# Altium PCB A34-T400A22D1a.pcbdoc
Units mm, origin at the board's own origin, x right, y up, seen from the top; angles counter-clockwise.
Board outline 74.15 x 49.73 mm, 2 copper layers (Top Layer, Bottom Layer); 2 components, 7 nets, 10 pads, 0 vias.
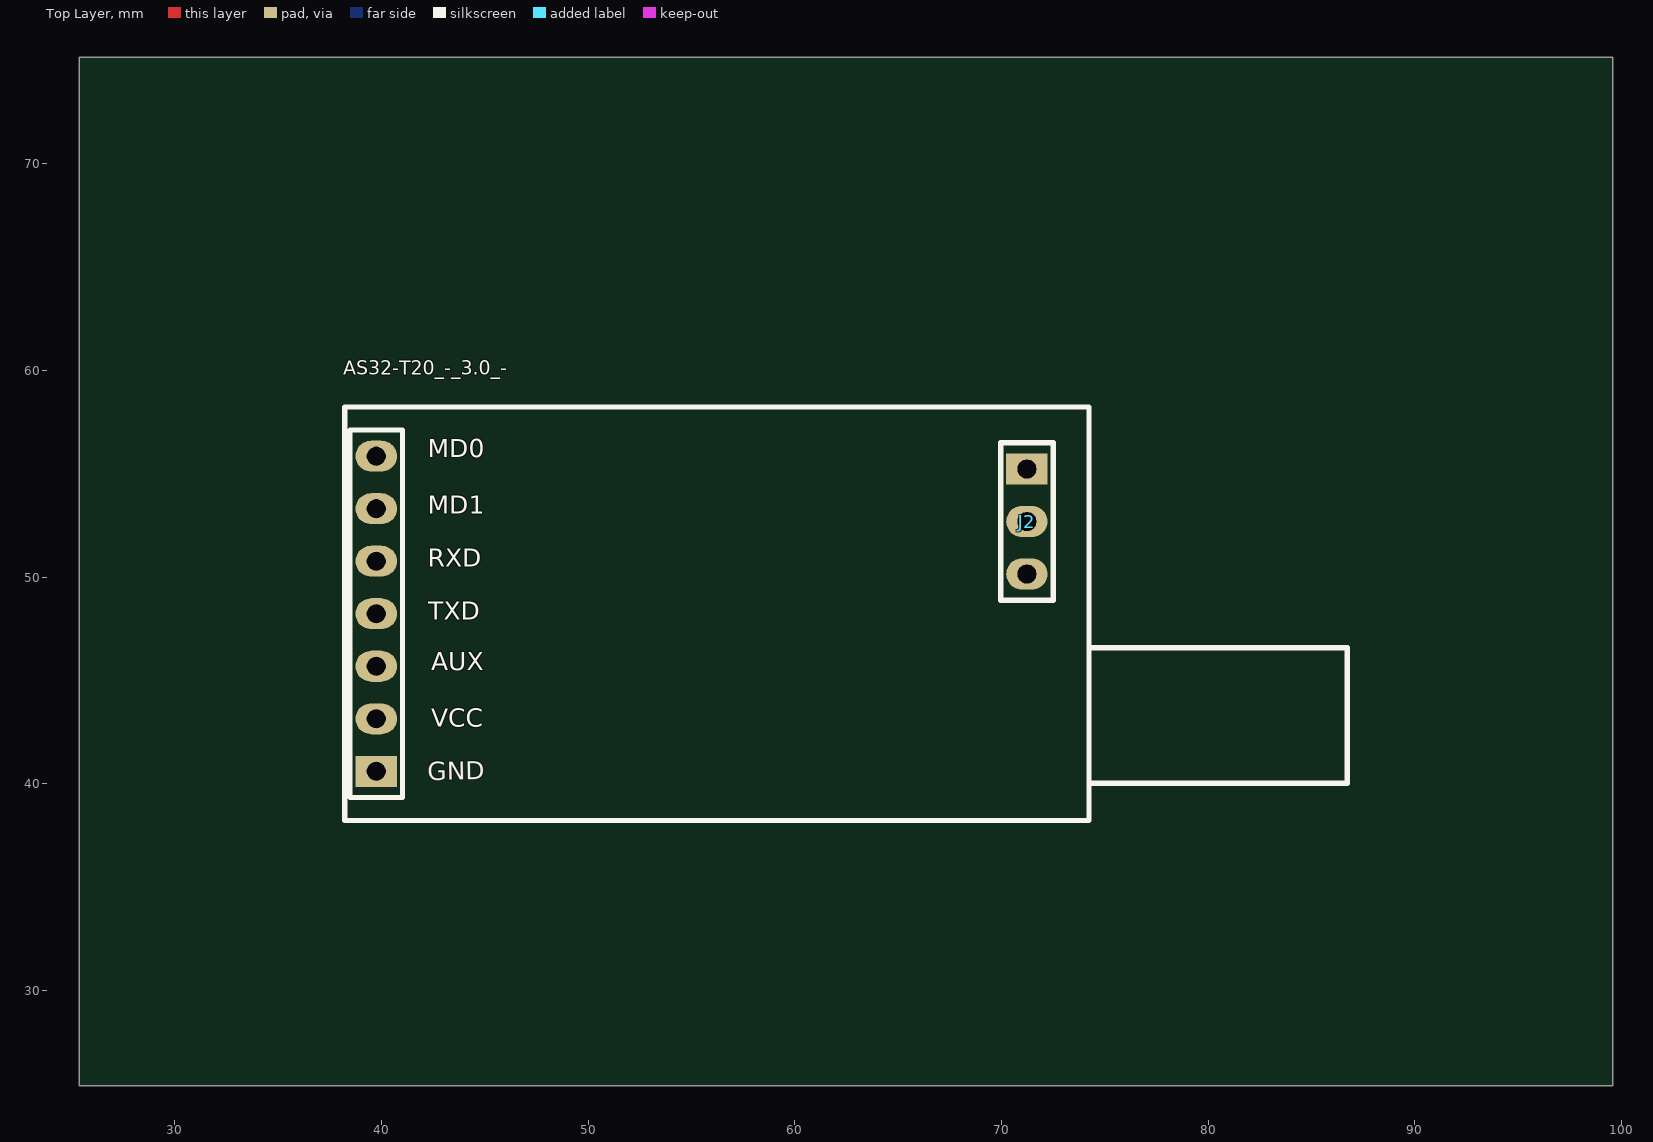
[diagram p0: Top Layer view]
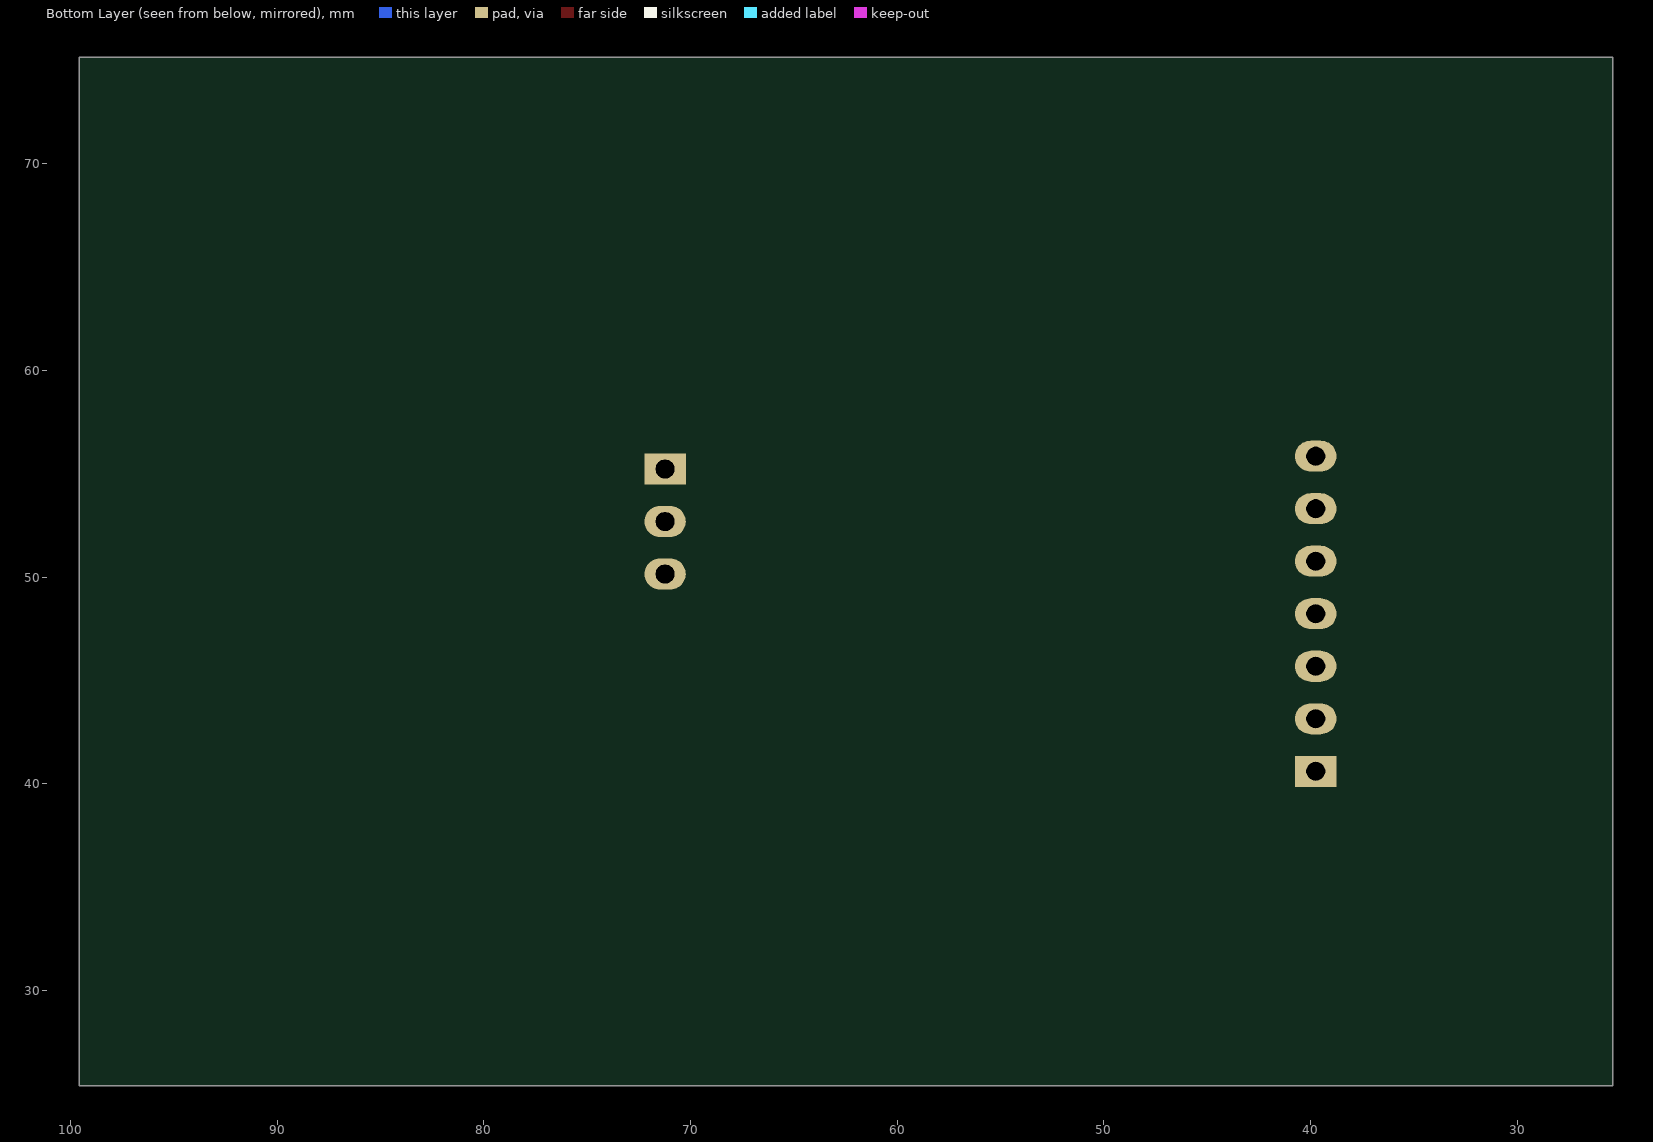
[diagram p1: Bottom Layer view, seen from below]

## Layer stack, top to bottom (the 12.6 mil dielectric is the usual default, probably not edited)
Top Layer: signal copper (thickness not stored)
Dielectric: dielectric 0.32, FR-4, Dk 4.8
Bottom Layer: signal copper (thickness not stored)

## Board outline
99.554,25.4 25.4,25.4 25.4,75.133 99.554,75.133

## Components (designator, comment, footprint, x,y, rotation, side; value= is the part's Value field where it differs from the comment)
AS32-T20_-_3.0_- "HEADER1X7-2.54MM" HEADER1X7-2.54MM 39.755,40.607 r0 top
J2 "HEADER1X3-2.54MM" HEADER1X3-2.54MM 71.227,55.227 r180 top

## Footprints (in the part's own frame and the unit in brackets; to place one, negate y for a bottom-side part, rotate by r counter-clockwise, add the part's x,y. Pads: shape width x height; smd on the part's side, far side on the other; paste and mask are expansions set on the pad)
HEADER1X3-2.54MM [mm]
  rect 2x1.5 hole 0.9 slot 0.905 at 0 deg: 1(0,0)
  oval 2x1.5 hole 0.9 slot 0.905 at 0 deg: 2(0,2.54) 3(0,5.08)
  silkscreen extent -1.27,-1.27 1.27,6.35
HEADER1X7-2.54MM [mm]
  rect 2x1.5 hole 0.9 slot 0.905 at 0 deg: 1(0,0)
  oval 2x1.5 hole 0.9 slot 0.905 at 0 deg: 2(0,2.54) 3(0,5.08) 4(0,7.62) 5(0,10.16) 6(0,12.7) 7(0,15.24)
  silkscreen extent -1.27,-1.27 1.27,16.51

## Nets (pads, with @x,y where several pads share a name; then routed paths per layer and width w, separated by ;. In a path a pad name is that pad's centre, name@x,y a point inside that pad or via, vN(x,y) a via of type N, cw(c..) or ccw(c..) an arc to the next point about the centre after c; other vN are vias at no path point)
S$7: 
S$9: 
S$11: 
S$13: 
S$15: 
S$17: 
S$19: 
pads on no net: AS32-T20_-_3.0_-.1 AS32-T20_-_3.0_-.2 AS32-T20_-_3.0_-.3 AS32-T20_-_3.0_-.4 AS32-T20_-_3.0_-.5 AS32-T20_-_3.0_-.6 AS32-T20_-_3.0_-.7 J2.1 J2.2 J2.3

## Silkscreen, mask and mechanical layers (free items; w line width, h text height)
Top Overlay:
  lines w0.254 net S$11: 74.227,38.227 74.227,58.227
  lines w0.254 net S$13: 38.227,38.227 74.227,38.227
  lines w0.254 net S$15: 74.226,40.028 78.524,40.028 86.726,40.028
  lines w0.254 net S$17: 86.727,40.027 86.727,46.577
  lines w0.254 net S$19: 74.227,46.577 86.727,46.577
  lines w0.254 net S$7: 38.227,38.227 38.227,58.227
  lines w0.254 net S$9: 38.227,58.227 74.227,58.227
  text "MD0" at 42.248,55.499 h1.5
  text "MD1" at 42.248,52.78 h1.5
  text "RXD" at 42.24,50.221 h1.5
  text "TXD" at 42.273,47.649 h1.5
  text "AUX" at 42.418,45.209 h1.5
  text "VCC" at 42.41,42.48 h1.5
  text "GND" at 42.235,39.878 h1.5 r1
Document:
  lines w0.003: 62.452,50.241 62.502,50.292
